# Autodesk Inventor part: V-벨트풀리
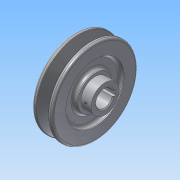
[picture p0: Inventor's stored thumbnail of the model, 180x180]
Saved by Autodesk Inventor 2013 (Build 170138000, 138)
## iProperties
Company: 한국ATC센터
Created: 2014-07
Part Number: V-벨트풀리
Document SubType Name: Modeling
Designer: KYOUNG IL JANG
Density: 2.71 g/cm^3
Material: 알루미늄 6061
Mass: 204.46 g
Surface Area: 234.121 cm^2
Volume: 75.4466 cm^3
Author: KYOUNG IL JANG
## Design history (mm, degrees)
sketch "스케치1"
  geometry: L1 (-15, 0)-(15, 0); L2 (-15, 0)-(-15, 17); L3 (-15, 17)-(-11, 17); L4 (-11, 17)-(-11, 29); L5 (-11, 29)-(-15, 29); L6 (-15, 29)-(-15, 42.5); L7 (-15, 42.5)-(-10.976, 42.5); L8 (-10.976, 42.5)-(-7.154, 30); L9 (-7.154, 30)-(-2.846, 30); L10 (-2.846, 30)-(0.976, 42.5); L11 (0.976, 42.5)-(5, 42.5); L12 (5, 42.5)-(5, 29); L13 (5, 29)-(1, 29); L14 (1, 29)-(1, 17); L15 (1, 17)-(5, 17); L16 (5, 17)-(5, 14); L17 (5, 14)-(15, 14); L18 (15, 14)-(15, 0); L19 (-9.6, 38)-(-0.4, 38); 2 further points
  constraints: 38 end point, 11 parallel, 7 collinear, 3 equal length, 3 perpendicular, 2 point on line, 1 coincident, 1 horizontal, 1 midpoint
  dimensions: "d0" = 30 distance of L1.start L1.end; "d1" = 4.5 distance between parallel lines of L7 L19; "d2" = 8 distance between parallel lines of L9 L19; "d3" = 9.2 distance of L19.start L19.end; "d4" = 34 deg angle of L10 L8; "d5" = 20 distance between parallel lines of L12 L6; "d6" = 76 diameter of L19 L1; "d7" = 4 distance of L2.end L3.end; "d8" = 34 diameter of L3 L1; "d9" = 58 diameter of L5 L1; "d10" = 28 diameter of L17 L1
revolve "회전1" sketch "스케치1" stored, may be unused: angle "d11" = 90 deg
sketch "스케치2"
  geometry: L1 (-2.5, 8.124)-(-2.5, 10.8); L2 (-2.5, 10.8)-(2.5, 10.8); L3 (2.5, 10.8)-(2.5, 8.124); A1 r 8.5 centre (0, 0) between (-2.5, 8.124) and (2.5, 8.124); 1 further point
  constraints: 6 end point, 2 parallel, 2 point on circle, 1 centre point, 1 coincident, 1 horizontal, 1 vertical
  dimensions: "d12" = 17 diameter of A1; "d13" = 5 distance of L1.end L2.end; "d14" = 19.3 dimension on A1 L2 (computed from d12)
extrude "돌출1" cut sketch "스케치2" stored distance "d15" = 10; taper "d16" = 0 deg
chamfer "모따기1" distance "d17" = 1; stored, may be unused: second distance "d18" = 2, angle "d19" = 45 deg
node "작업 평면1"
sketch "스케치3"
  geometry: L1 (5, -14)-(5, 14) reference; 3 further points
  constraints: 1 horizontal alignment, 1 midpoint
  dimensions: "d20" = 5 distance from line of L1 point (0, 0)
hole "구멍1" sketch "스케치3" at (0, 0) diameter "d21" = 3.242; stored, may be unused: countersink angle "d25" = 90 deg, drill point angle "d27" = 118 deg; dims "d22" = 6, "d23" = 4, "d24" = 2, "d26" = 8
fillet "모깎기1" dims "d28" = 3, "d29" = 2, "d30" = 0.5, "d31" = 1
node "솔리드1"
